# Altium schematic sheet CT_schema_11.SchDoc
size 278 x 170 mm
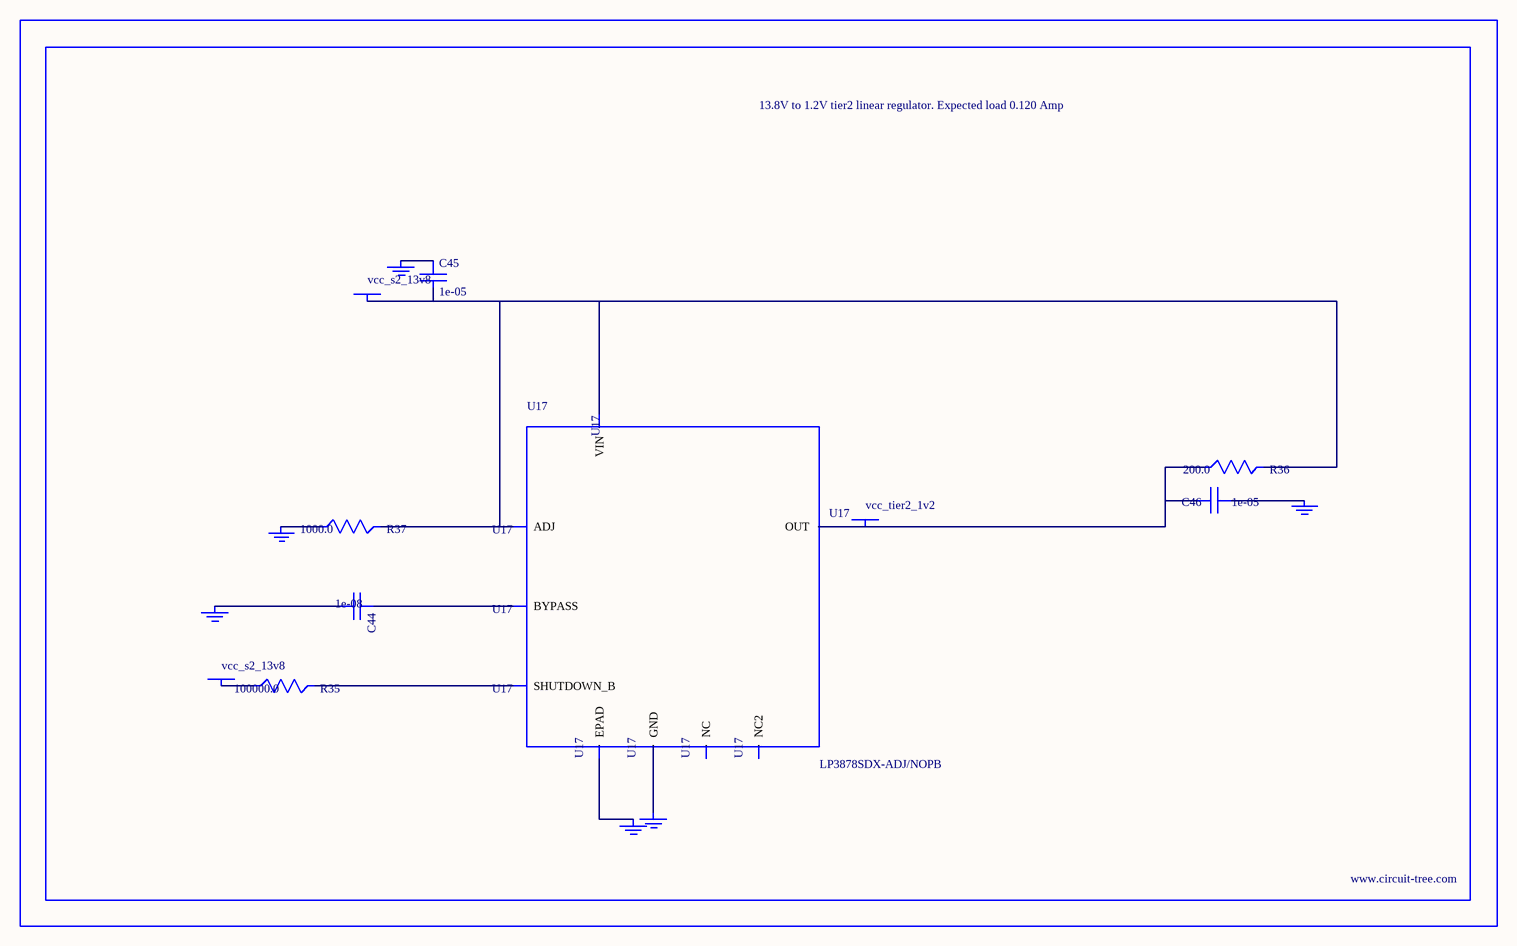
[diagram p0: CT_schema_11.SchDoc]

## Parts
BORDER10  (no value)
C44  1e-08  [C0402]
C45  1e-05  [C1210]
C46  1e-05  [C0805]
GND_INSTANCE_10_0  (no value)
GND_INSTANCE_10_1  (no value)
GND_INSTANCE_10_2  (no value)
GND_INSTANCE_10_3  (no value)
GND_INSTANCE_10_4  (no value)
GND_INSTANCE_10_5  (no value)
POWER_INSTANCE_10_0  vcc_s2_13v8
POWER_INSTANCE_10_1  vcc_s2_13v8
POWER_INSTANCE_10_2  vcc_tier2_1v2
R35  100000.0  [R0603]
R36  200.0  [R0603]
R37  1000.0  [R0603]
U17  LP3878SDX-ADJ/NOPB  [WSON-8]

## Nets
NetC44_1: C44.1 U17.1(BYPASS)
NetC44_2: C44.2 GND_INSTANCE_10_0.0(GND)
NetC45_1: C45.1 GND_INSTANCE_10_1.0(GND)
NetC45_2: C45.2 POWER_INSTANCE_10_0.0(PWR) R36.2 R37.2 U17.4(VIN) U17.6(ADJ)
NetC46_1: C46.1 GND_INSTANCE_10_2.0(GND)
NetC46_2: C46.2 POWER_INSTANCE_10_2.0(PWR) R36.1 U17.5(OUT)
NetGND_INSTANCE_10_3_0: GND_INSTANCE_10_3.0(GND) R37.1
NetGND_INSTANCE_10_4_0: GND_INSTANCE_10_4.0(GND) U17.PAD(EPAD)
NetGND_INSTANCE_10_5_0: GND_INSTANCE_10_5.0(GND) U17.3(GND)
NetPOWER_INSTANCE_10_1_0: POWER_INSTANCE_10_1.0(PWR) R35.1
NetR35_2: R35.2 U17.8(SHUTDOWN_B)

Not connected (* = marked no-connect by the designer): U17 2(NC) 7(NC2)

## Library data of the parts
BORDER10 = BORDER_PAGE10
C44 = C0402C103K3RAC
C45 = C1210C106K5PACTU
C46 = GRM219R60J106ME19D
GND_INSTANCE_10_0-GND_INSTANCE_10_5 = GND
POWER_INSTANCE_10_0-POWER_INSTANCE_10_2 = PWR
R35 = RC0603JR-07100KL
R36 = RC0603JR-07200RL
R37 = RC0603JR-071KL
